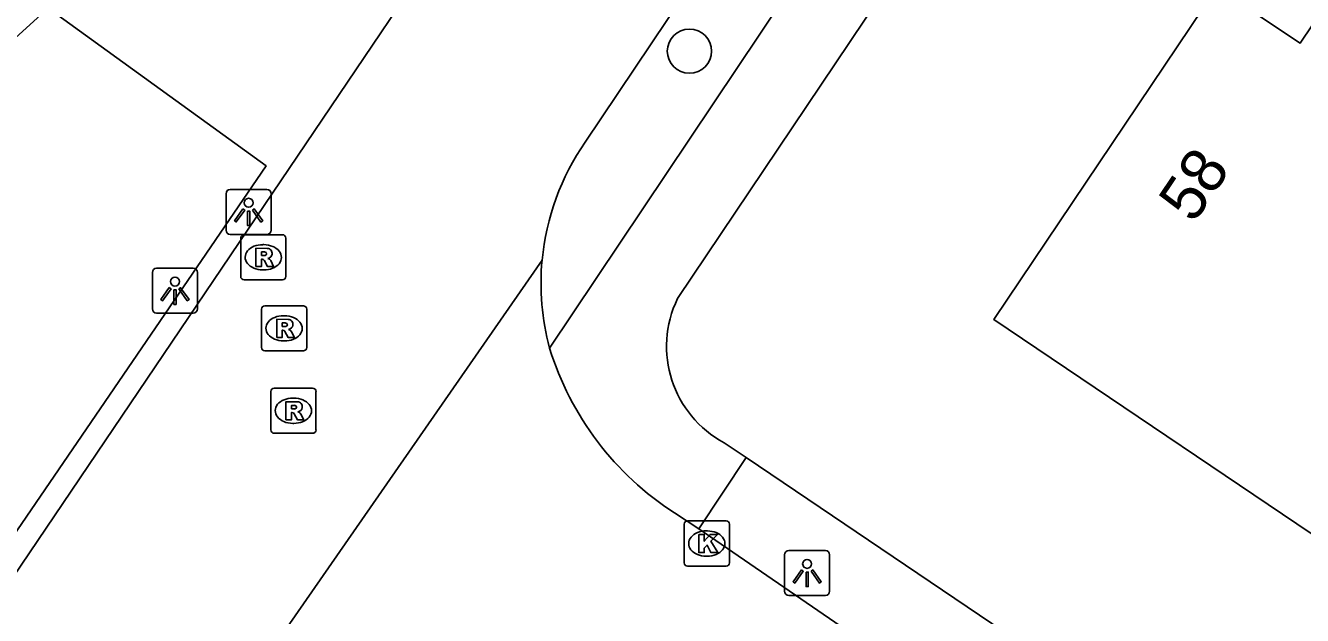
# Model space of a CAD drawing. Extents: x 163268 to 164360, y 381529 to 382285.
# Drawn here: x 164058.56 to 164086.82, y 381787.13 to 381800.19 of the extents above; entities that cross this region are included whole.
import ezdxf

# ---------------------------------------------------------------- set-up
doc = ezdxf.new("R2010")
doc.units = 0
for name, color, linetype in [('IMGEO_Boom', 7, 'Continuous'), ('IMGEO_Haag', 7, 'Continuous'), ('IMGEO_Kolk', 7, 'Continuous'), ('IMGEO_Lichtpunt', 7, 'Continuous'), ('IMGEO_Pand', 7, 'Continuous'), ('IMGEO_Pand_nummerreeks', 7, 'Continuous'), ('IMGEO_Rijbaan_lokaal_open', 7, 'Continuous'), ('IMGEO_Rioolput', 7, 'Continuous'), ('IMGEO_Voetpad_halfverhard', 7, 'Continuous'), ('IMGEO_Voetpad_open', 7, 'Continuous')]:
    doc.layers.add(name, color=color, linetype=linetype)

msp = doc.modelspace()

# ---------------------------------------------------------------- linework, layer by layer
at = {"layer": 'IMGEO_Boom'}
msp.add_circle((164073.251, 381799.621), 0.489, dxfattribs=at)
at = {"layer": 'IMGEO_Haag'}
msp.add_lwpolyline([(164050.062, 381793.119), (164050.389, 381792.767), (164052.578, 381794.606), (164053.537, 381793.534), (164054.076, 381794.086), (164053.139, 381795.193), (164059.059, 381800.576), (164063.883, 381797.08), (164057.656, 381787.98), (164058.095, 381787.701)], dxfattribs=at)
at = {"layer": 'IMGEO_Kolk'}
for p, q in [((164073.135, 381788.299), (164073.135, 381789.151)), ((164073.21, 381789.225), (164074.062, 381789.225)), ((164074.136, 381789.151), (164074.136, 381788.299)), ((164073.623, 381789.005), (164073.648, 381789.005)), ((164073.646, 381788.445), (164073.621, 381788.445)), ((164074.062, 381788.225), (164073.21, 381788.225))]:
    msp.add_line(p, q, dxfattribs=at)
for points in [[(164073.135, 381788.299), (164073.135, 381789.151)], [(164073.21, 381789.225), (164074.062, 381789.225)], [(164074.136, 381789.151), (164074.136, 381788.299)], [(164073.456, 381788.925), (164073.579, 381788.925), (164073.579, 381788.774), (164073.709, 381788.925), (164073.873, 381788.925), (164073.727, 381788.774), (164073.88, 381788.525), (164073.728, 381788.525), (164073.643, 381788.689), (164073.579, 381788.622), (164073.579, 381788.525), (164073.456, 381788.525), (164073.456, 381788.925)], [(164074.062, 381788.225), (164073.21, 381788.225)]]:
    msp.add_lwpolyline(points, dxfattribs=at)
for centre, start, end in [((164073.212, 381789.149), 91.552, 178.448), ((164073.212, 381789.149), 91.552, 178.448), ((164074.06, 381789.149), 1.552, 88.448), ((164074.06, 381789.149), 1.552, 88.448), ((164073.212, 381788.301), 181.552, 268.448), ((164073.212, 381788.301), 181.552, 268.448), ((164074.06, 381788.301), 271.552, 358.448), ((164074.06, 381788.301), 271.552, 358.448)]:
    msp.add_arc(centre, 0.0765, start, end, dxfattribs=at)
for centre, major_axis, ratio, start_param, end_param in [((164073.622, 381788.725), (-0.387, 0.002), 0.722429, 4.712389, 7.853982), ((164073.647, 381788.725), (-0.39, 0.002), 0.717154, 1.570796, 4.712389)]:
    msp.add_ellipse(centre, major_axis=major_axis, ratio=ratio, start_param=start_param, end_param=end_param, dxfattribs=at)
at = {"layer": 'IMGEO_Lichtpunt'}
for p, q in [((164063.899, 381796.562), (164063.091, 381796.562)), ((164063.899, 381796.562), (164063.091, 381796.562)), ((164062.997, 381796.467), (164062.997, 381795.66)), ((164062.997, 381796.467), (164062.997, 381795.66)), ((164063.993, 381795.66), (164063.993, 381796.467)), ((164063.993, 381795.66), (164063.993, 381796.467)), ((164063.091, 381795.566), (164063.899, 381795.566)), ((164063.091, 381795.566), (164063.899, 381795.566)), ((164062.268, 381794.819), (164061.46, 381794.819)), ((164062.268, 381794.819), (164061.46, 381794.819)), ((164061.366, 381794.724), (164061.366, 381793.917)), ((164061.366, 381794.724), (164061.366, 381793.917)), ((164062.362, 381793.917), (164062.362, 381794.724)), ((164062.362, 381793.917), (164062.362, 381794.724)), ((164061.46, 381793.823), (164062.268, 381793.823)), ((164061.46, 381793.823), (164062.268, 381793.823)), ((164075.358, 381788.477), (164075.358, 381787.67)), ((164075.358, 381788.477), (164075.358, 381787.67)), ((164076.26, 381788.572), (164075.452, 381788.572)), ((164076.26, 381788.572), (164075.452, 381788.572)), ((164076.354, 381787.67), (164076.354, 381788.477)), ((164076.354, 381787.67), (164076.354, 381788.477)), ((164075.452, 381787.576), (164076.26, 381787.576)), ((164075.452, 381787.576), (164076.26, 381787.576))]:
    msp.add_line(p, q, dxfattribs=at)
for points in [[(164063.371, 381796.131), (164063.41, 381796.103), (164063.222, 381795.841), (164063.184, 381795.868), (164063.371, 381796.131)], [(164063.473, 381796.083), (164063.52, 381796.083), (164063.52, 381795.761), (164063.473, 381795.761), (164063.473, 381796.083)], [(164063.583, 381796.103), (164063.621, 381796.13), (164063.808, 381795.868), (164063.769, 381795.84), (164063.583, 381796.103)], [(164061.74, 381794.388), (164061.779, 381794.36), (164061.591, 381794.098), (164061.553, 381794.125), (164061.74, 381794.388)], [(164061.842, 381794.34), (164061.889, 381794.34), (164061.889, 381794.018), (164061.842, 381794.018), (164061.842, 381794.34)], [(164061.952, 381794.36), (164061.99, 381794.387), (164062.177, 381794.125), (164062.138, 381794.097), (164061.952, 381794.36)], [(164075.732, 381788.141), (164075.771, 381788.113), (164075.583, 381787.851), (164075.545, 381787.878), (164075.732, 381788.141)], [(164075.834, 381788.093), (164075.881, 381788.093), (164075.881, 381787.771), (164075.834, 381787.771), (164075.834, 381788.093)], [(164075.944, 381788.113), (164075.982, 381788.14), (164076.169, 381787.878), (164076.13, 381787.85), (164075.944, 381788.113)]]:
    msp.add_lwpolyline(points, dxfattribs=at)
for centre in [(164063.496, 381796.265), (164061.865, 381794.522), (164075.857, 381788.275)]:
    msp.add_circle(centre, 0.0994, dxfattribs=at)
for centre, start, end in [((164063.091, 381796.467), 90, 180), ((164063.091, 381796.467), 90, 180), ((164063.899, 381796.467), 0, 90), ((164063.899, 381796.467), 0, 90), ((164063.091, 381795.66), 180, 270), ((164063.091, 381795.66), 180, 270), ((164063.899, 381795.66), 270, 0), ((164063.899, 381795.66), 270, 360), ((164061.46, 381794.724), 90, 180), ((164061.46, 381794.724), 90, 180), ((164062.268, 381794.724), 0, 90), ((164062.268, 381794.724), 0, 90), ((164061.46, 381793.917), 180, 270), ((164061.46, 381793.917), 180, 270), ((164062.268, 381793.917), 270, 0), ((164062.268, 381793.917), 270, 360), ((164075.452, 381788.477), 90, 180), ((164075.452, 381788.477), 90, 180), ((164076.26, 381788.477), 0, 90), ((164076.26, 381788.477), 0, 90), ((164075.452, 381787.67), 180, 270), ((164075.452, 381787.67), 180, 270), ((164076.26, 381787.67), 270, 0), ((164076.26, 381787.67), 270, 360)]:
    msp.add_arc(centre, 0.0946, start, end, dxfattribs=at)
at = {"layer": 'IMGEO_Pand'}
msp.add_lwpolyline([(164102.627, 381800.006), (164100.505, 381796.865), (164096.94, 381799.298), (164093.014, 381793.476), (164092.285, 381793.964), (164088.306, 381788.075), (164079.985, 381793.684), (164084.926, 381801.027), (164086.769, 381799.8), (164088.924, 381803.005), (164093.322, 381800.037), (164096.197, 381804.333), (164102.627, 381800.006)], dxfattribs=at)
at = {"layer": 'IMGEO_Rijbaan_lokaal_open'}
for points in [[(164074.949, 381812.656), (164058.095, 381787.701)], [(164075.329, 381804.141), (164070.945, 381797.609)], [(164069.991, 381794.998), (164063.851, 381786.159)], [(164073.456, 381789.047), (164072.921, 381789.401)], [(164121.372, 381756.832), (164078.354, 381785.697), (164073.456, 381789.047)]]:
    msp.add_lwpolyline(points, dxfattribs=at)
for centre, radius, start, end in [((164075.467, 381794.477), 5.5, 145.2922, 174.5655), ((164075.445, 381794.48), 5.478, 174.5711, 195.1169), ((164076.551, 381795.023), 6.692, 197.1385, 237.1518)]:
    msp.add_arc(centre, radius, start, end, dxfattribs=at)
at = {"layer": 'IMGEO_Rioolput'}
for p, q in [((164063.32, 381794.633), (164063.32, 381795.485)), ((164063.395, 381795.559), (164064.247, 381795.559)), ((164064.321, 381795.485), (164064.321, 381794.633)), ((164063.808, 381795.339), (164063.833, 381795.339)), ((164064.247, 381794.559), (164063.395, 381794.559)), ((164063.831, 381794.779), (164063.806, 381794.779)), ((164063.855, 381793.987), (164064.707, 381793.987)), ((164063.78, 381793.061), (164063.78, 381793.913)), ((164064.268, 381793.767), (164064.293, 381793.767)), ((164064.781, 381793.913), (164064.781, 381793.061)), ((164064.291, 381793.207), (164064.266, 381793.207)), ((164064.707, 381792.987), (164063.855, 381792.987)), ((164063.986, 381791.238), (164063.986, 381792.09)), ((164064.061, 381792.164), (164064.913, 381792.164)), ((164064.987, 381792.09), (164064.987, 381791.238)), ((164064.474, 381791.944), (164064.499, 381791.944)), ((164064.913, 381791.164), (164064.061, 381791.164)), ((164064.497, 381791.384), (164064.472, 381791.384))]:
    msp.add_line(p, q, dxfattribs=at)
for points in [[(164063.32, 381794.633), (164063.32, 381795.485)], [(164063.395, 381795.559), (164064.247, 381795.559)], [(164064.321, 381795.485), (164064.321, 381794.633)], [(164063.909, 381795.257), (164063.657, 381795.259), (164063.657, 381794.859)], [(164063.835, 381795.178), (164063.781, 381795.178), (164063.781, 381795.097)], [(164063.781, 381795.097), (164063.833, 381795.097)], [(164063.657, 381794.859), (164063.781, 381794.859), (164063.781, 381795.021), (164063.792, 381795.021)], [(164063.839, 381794.992), (164063.91, 381794.859), (164064.05, 381794.859), (164063.985, 381794.985)], [(164064.247, 381794.559), (164063.395, 381794.559)], [(164063.855, 381793.987), (164064.707, 381793.987)], [(164063.78, 381793.061), (164063.78, 381793.913)], [(164064.369, 381793.685), (164064.117, 381793.687), (164064.117, 381793.287)], [(164064.781, 381793.913), (164064.781, 381793.061)], [(164064.117, 381793.287), (164064.241, 381793.287), (164064.241, 381793.449), (164064.252, 381793.449)], [(164064.295, 381793.606), (164064.241, 381793.606), (164064.241, 381793.525)], [(164064.241, 381793.525), (164064.293, 381793.525)], [(164064.299, 381793.42), (164064.37, 381793.287), (164064.51, 381793.287), (164064.445, 381793.413)], [(164064.707, 381792.987), (164063.855, 381792.987)], [(164063.986, 381791.238), (164063.986, 381792.09)], [(164064.061, 381792.164), (164064.913, 381792.164)], [(164064.987, 381792.09), (164064.987, 381791.238)], [(164064.575, 381791.862), (164064.323, 381791.864), (164064.323, 381791.464)], [(164064.501, 381791.783), (164064.447, 381791.783), (164064.447, 381791.702)], [(164064.447, 381791.702), (164064.499, 381791.702)], [(164064.323, 381791.464), (164064.447, 381791.464), (164064.447, 381791.626), (164064.458, 381791.626)], [(164064.505, 381791.597), (164064.576, 381791.464), (164064.716, 381791.464), (164064.651, 381791.59)], [(164064.913, 381791.164), (164064.061, 381791.164)]]:
    msp.add_lwpolyline(points, dxfattribs=at)
for centre, radius, start, end in [((164063.397, 381795.483), 0.0765, 91.552, 178.448), ((164063.397, 381795.483), 0.0765, 91.552, 178.448), ((164064.245, 381795.483), 0.0765, 1.552, 88.448), ((164064.245, 381795.483), 0.0765, 1.552, 88.448), ((164063.817, 381795.286), 0.19, 274.7715, 282.9687), ((164063.841, 381795.082), 0.0964, 77.0061, 93.1865), ((164063.855, 381795.139), 0.0378, 276.6634, 79.6772), ((164063.908, 381795.147), 0.109, 350.3612, 89.416), ((164063.906, 381795.147), 0.112, 277.5842, 350.9817), ((164063.791, 381794.968), 0.0533, 26.0293, 88.6989), ((164063.89, 381794.932), 0.108, 29.5134, 73.7905), ((164063.397, 381794.635), 0.0765, 181.552, 268.448), ((164063.397, 381794.635), 0.0765, 181.552, 268.448), ((164064.245, 381794.635), 0.0765, 271.552, 358.448), ((164064.245, 381794.635), 0.0765, 271.552, 358.448), ((164063.857, 381793.911), 0.0765, 91.552, 178.448), ((164063.857, 381793.911), 0.0765, 91.552, 178.448), ((164064.705, 381793.911), 0.0765, 1.552, 88.448), ((164064.705, 381793.911), 0.0765, 1.552, 88.448), ((164064.368, 381793.575), 0.109, 350.3612, 89.416), ((164064.251, 381793.396), 0.0533, 26.0293, 88.6989), ((164064.277, 381793.714), 0.19, 274.7715, 282.9687), ((164064.301, 381793.51), 0.0964, 77.0061, 93.1865), ((164064.315, 381793.567), 0.0378, 276.6634, 79.6772), ((164064.366, 381793.575), 0.112, 277.5842, 350.9817), ((164064.35, 381793.36), 0.108, 29.5134, 73.7905), ((164063.857, 381793.063), 0.0765, 181.552, 268.448), ((164063.857, 381793.063), 0.0765, 181.552, 268.448), ((164064.705, 381793.063), 0.0765, 271.552, 358.448), ((164064.705, 381793.063), 0.0765, 271.552, 358.448), ((164064.063, 381792.088), 0.0765, 91.552, 178.448), ((164064.063, 381792.088), 0.0765, 91.552, 178.448), ((164064.911, 381792.088), 0.0765, 1.552, 88.448), ((164064.911, 381792.088), 0.0765, 1.552, 88.448), ((164064.483, 381791.891), 0.19, 274.7715, 282.9687), ((164064.507, 381791.687), 0.0964, 77.0061, 93.1865), ((164064.521, 381791.744), 0.0378, 276.6634, 79.6772), ((164064.574, 381791.752), 0.109, 350.3612, 89.416), ((164064.572, 381791.752), 0.112, 277.5842, 350.9817), ((164064.457, 381791.573), 0.0533, 26.0293, 88.6989), ((164064.556, 381791.537), 0.108, 29.5134, 73.7905), ((164064.063, 381791.24), 0.0765, 181.552, 268.448), ((164064.063, 381791.24), 0.0765, 181.552, 268.448), ((164064.911, 381791.24), 0.0765, 271.552, 358.448), ((164064.911, 381791.24), 0.0765, 271.552, 358.448)]:
    msp.add_arc(centre, radius, start, end, dxfattribs=at)
for centre, major_axis, ratio, start_param, end_param in [((164063.807, 381795.059), (-0.387, 0.002), 0.722429, 4.712389, 7.853982), ((164063.832, 381795.059), (-0.39, 0.002), 0.717154, 1.570796, 4.712389), ((164064.267, 381793.487), (-0.387, 0.002), 0.722429, 4.712389, 7.853982), ((164064.292, 381793.487), (-0.39, 0.002), 0.717154, 1.570796, 4.712389), ((164064.473, 381791.664), (-0.387, 0.002), 0.722429, 4.712389, 7.853982), ((164064.498, 381791.664), (-0.39, 0.002), 0.717154, 1.570796, 4.712389)]:
    msp.add_ellipse(centre, major_axis=major_axis, ratio=ratio, start_param=start_param, end_param=end_param, dxfattribs=at)
at = {"layer": 'IMGEO_Voetpad_halfverhard'}
msp.add_lwpolyline([(164074.507, 381790.627), (164088.358, 381781.266), (164122.212, 381758.384)], dxfattribs=at)
at = {"layer": 'IMGEO_Voetpad_open'}
for points in [[(164093.902, 381825.629), (164084.278, 381811.341), (164084.454, 381811.217), (164072.99, 381794.147)], [(164070.156, 381793.051), (164076.892, 381803.113), (164075.329, 381804.141)], [(164074.023, 381790.953), (164074.507, 381790.627)], [(164074.507, 381790.627), (164073.456, 381789.047)]]:
    msp.add_lwpolyline(points, dxfattribs=at)
msp.add_arc((164075.169, 381793.088), 2.423, 154.0726, 241.7717, dxfattribs=at)

# ---------------------------------------------------------------- texts
at = {"layer": 'IMGEO_Pand_nummerreeks'}
msp.add_text('58', height=1, rotation=56.0639, dxfattribs=at).set_placement((164084.411, 381795.783))

doc.saveas('drawing.dxf')
